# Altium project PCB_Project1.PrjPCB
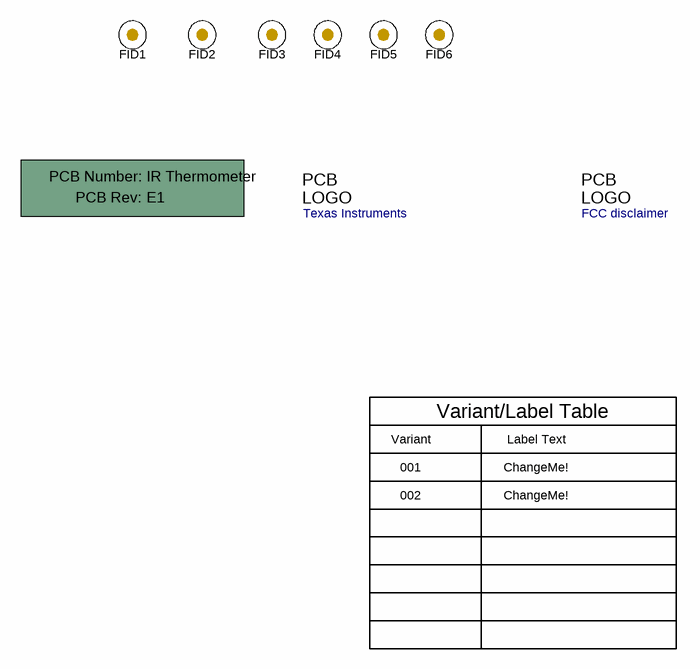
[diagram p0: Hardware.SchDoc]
CopyrightYear: 2018; PCB_Layout: Abhishek Vishwa; PCB_Rev: E1; PRJ_Customer: Public Release; PRJ_Engineer: Abhishek Vishwa; PRJ_Number: IR Thermometer; PRJ_Title: IR Thermometer Design; SCH_Rev: E1; TechSupport: http://www.ti.com/support; TID: N/A
2 sheets, 117 parts. Net scope: flat (ports and power ports of the same name join across sheets).
Board file: PCB.PcbDoc
Sheets:
  Hardware.SchDoc
  Host Controller Section_1.SchDoc

## Sheet Hardware.SchDoc
size 431 x 279 mm; Date: Not shown in title block; ApprovedBy: Not shown in title block; CheckedBy: Not shown in title block; Author: Not shown in title block; CompanyName: Not shown in title block; Engineer: Not shown in title block; Organization: Not shown in title block; Address1: Not shown in title block; Address2: Not shown in title block; Address3: Not shown in title block; Address4: Not shown in title block; DocumentNumber: 5; Revision: Use project parameter SCH_Rev; SheetNumber: 5; SheetTotal: 3; PageSetup: Record=PageOptions¦CenterHorizontal=True¦CenterVertical=True¦PrintScale=1.00¦XCorrection=1.00¦YCorrection=1.00¦PrintKind=0¦BorderSize=5000000¦LeftOffset=0¦BottomOffset=0¦Orientation=2¦PaperLength=1000¦PaperWidth=1000¦Scale=100¦PaperSource=15¦PrintQuality=600¦MediaType=1¦DitherType=10¦PaperKind=Letter¦PrintScaleMode=1

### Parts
!PCB1  Printed Circuit Board  (value not drawn)  (mechanical)
FID1  Fiducial  [Fiducial10-20]  (value not drawn)
FID2  Fiducial  [Fiducial10-20]  (value not drawn)
FID3  Fiducial  [Fiducial10-20]  (value not drawn)
FID4  Fiducial  [Fiducial10-20]  (value not drawn)
FID5  Fiducial  [Fiducial10-20]  (value not drawn)
FID6  Fiducial  [Fiducial10-20]  (value not drawn)
Logo2  Texas Instruments  [TI_Stacked_Overlay_Small]  (no BOM)
Logo3  FCC disclaimer  [FCC_disclaimer]  (no BOM)

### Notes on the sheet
- Variant
- Variant/Label Table
- Label Text
- 001
- 002
- ChangeMe!

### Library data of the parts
!PCB1 = CMP-0003618-2: Manufacturer: Any; PartNumber: IR Thermometer
FID1-FID6 = CMP-0077181-1: Fiducial mark.  There is nothing to buy or mount.
Logo2 = CMP-0074838-1: Texas Instrument Corporate Signature; SymbolCreator: a0412235; Lib Reference: TI_Logo
Logo3 = CMP-0074847-1: FCC_disclaimer

## Sheet Host Controller Section_1.SchDoc
size A2; DocumentNumber: 4; SheetNumber: 4; PageSetup: Record=PageOptions¦CenterHorizontal=True¦CenterVertical=True¦PrintScale=0.69¦XCorrection=1.00¦YCorrection=1.00¦PrintKind=0¦BorderSize=5000000¦LeftOffset=0¦BottomOffset=0¦Orientation=2¦PaperLength=1000¦PaperWidth=1000¦Scale=100¦PaperSource=15¦PrintQuality=600¦MediaType=1¦DitherType=10¦PaperKind=Letter¦PrintScaleMode=1
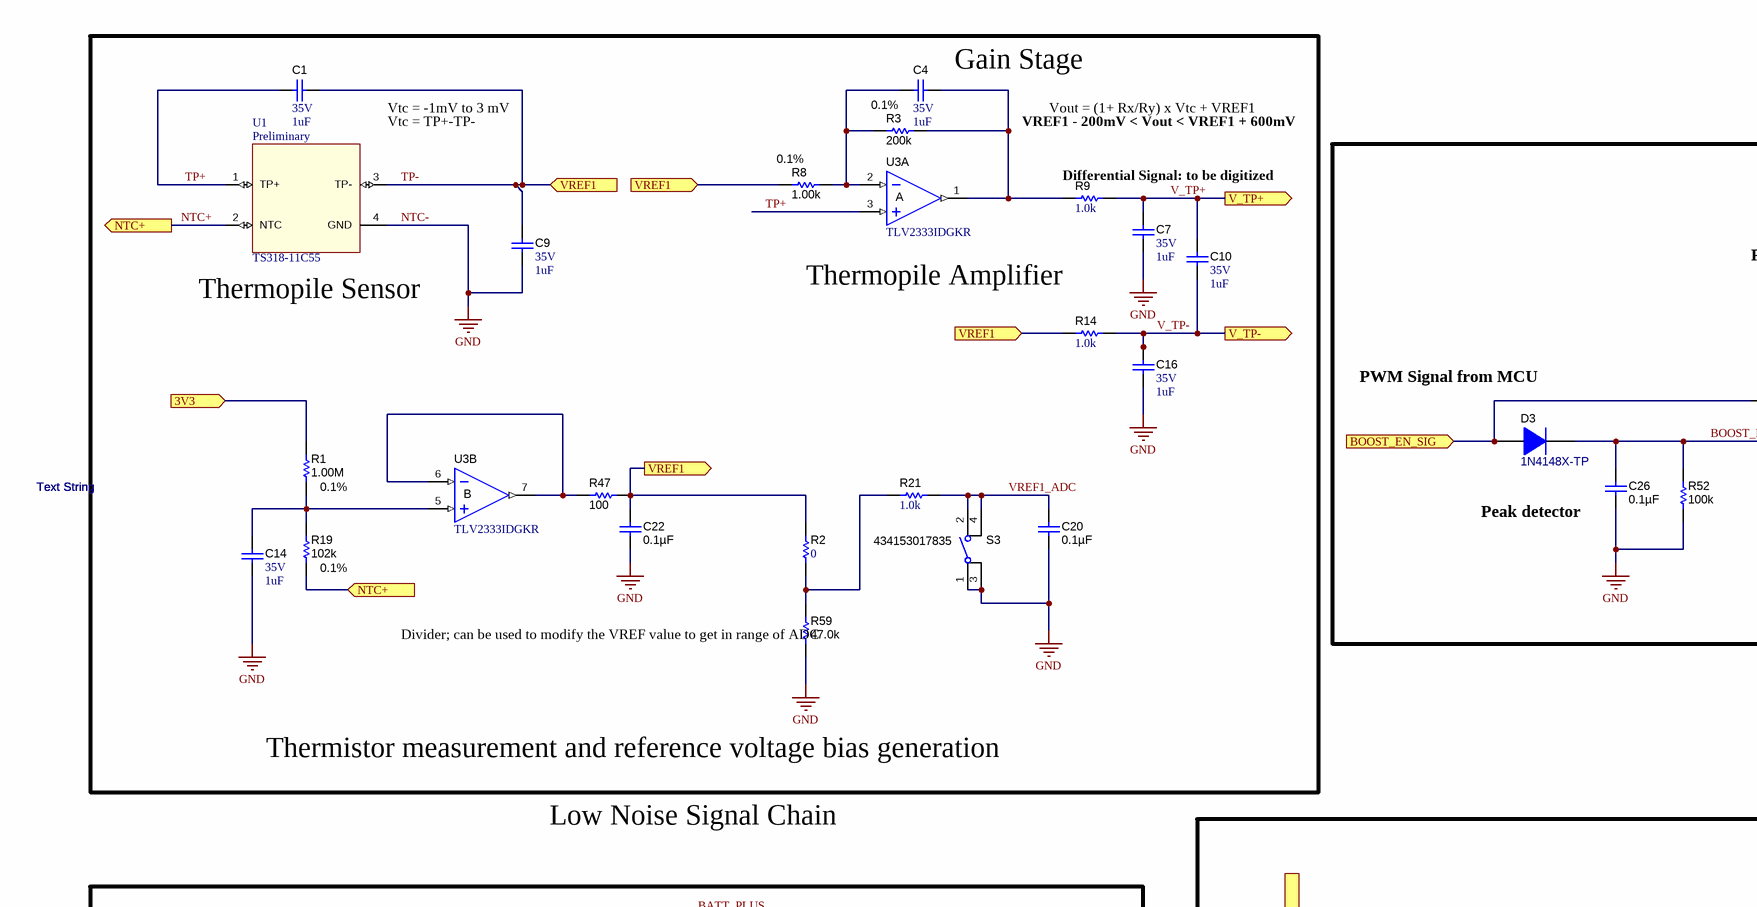
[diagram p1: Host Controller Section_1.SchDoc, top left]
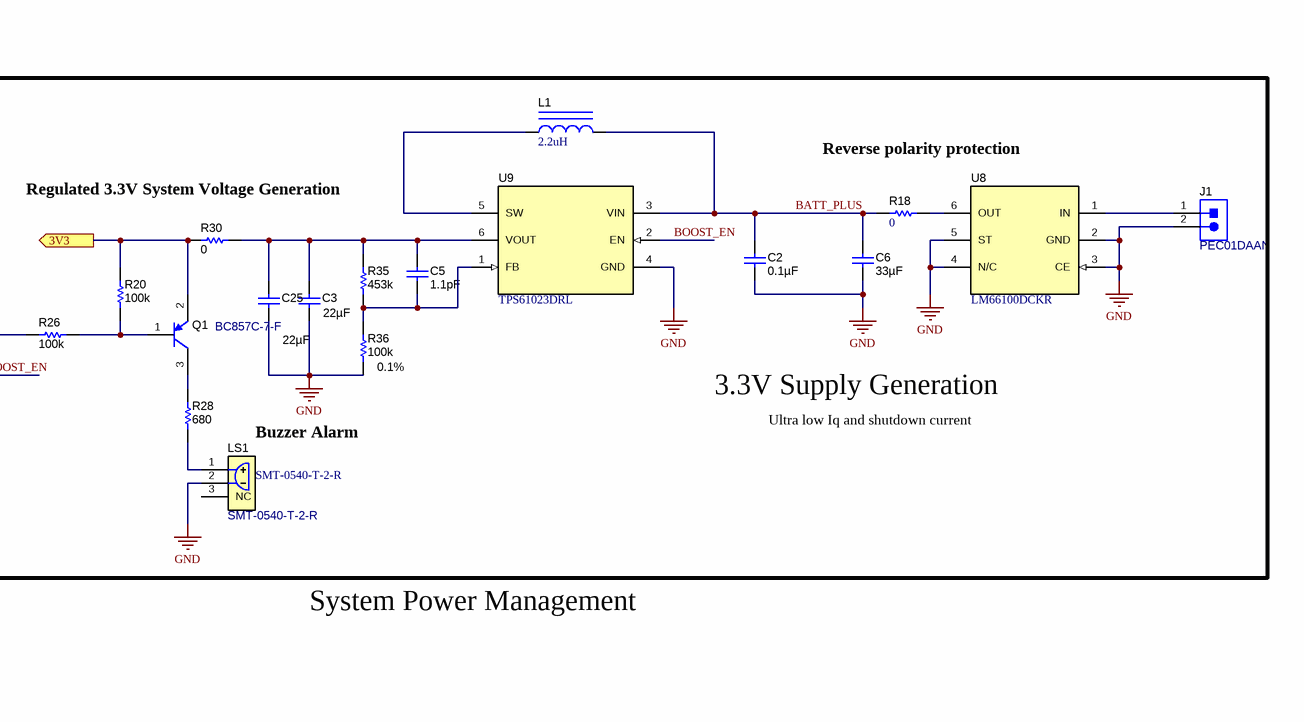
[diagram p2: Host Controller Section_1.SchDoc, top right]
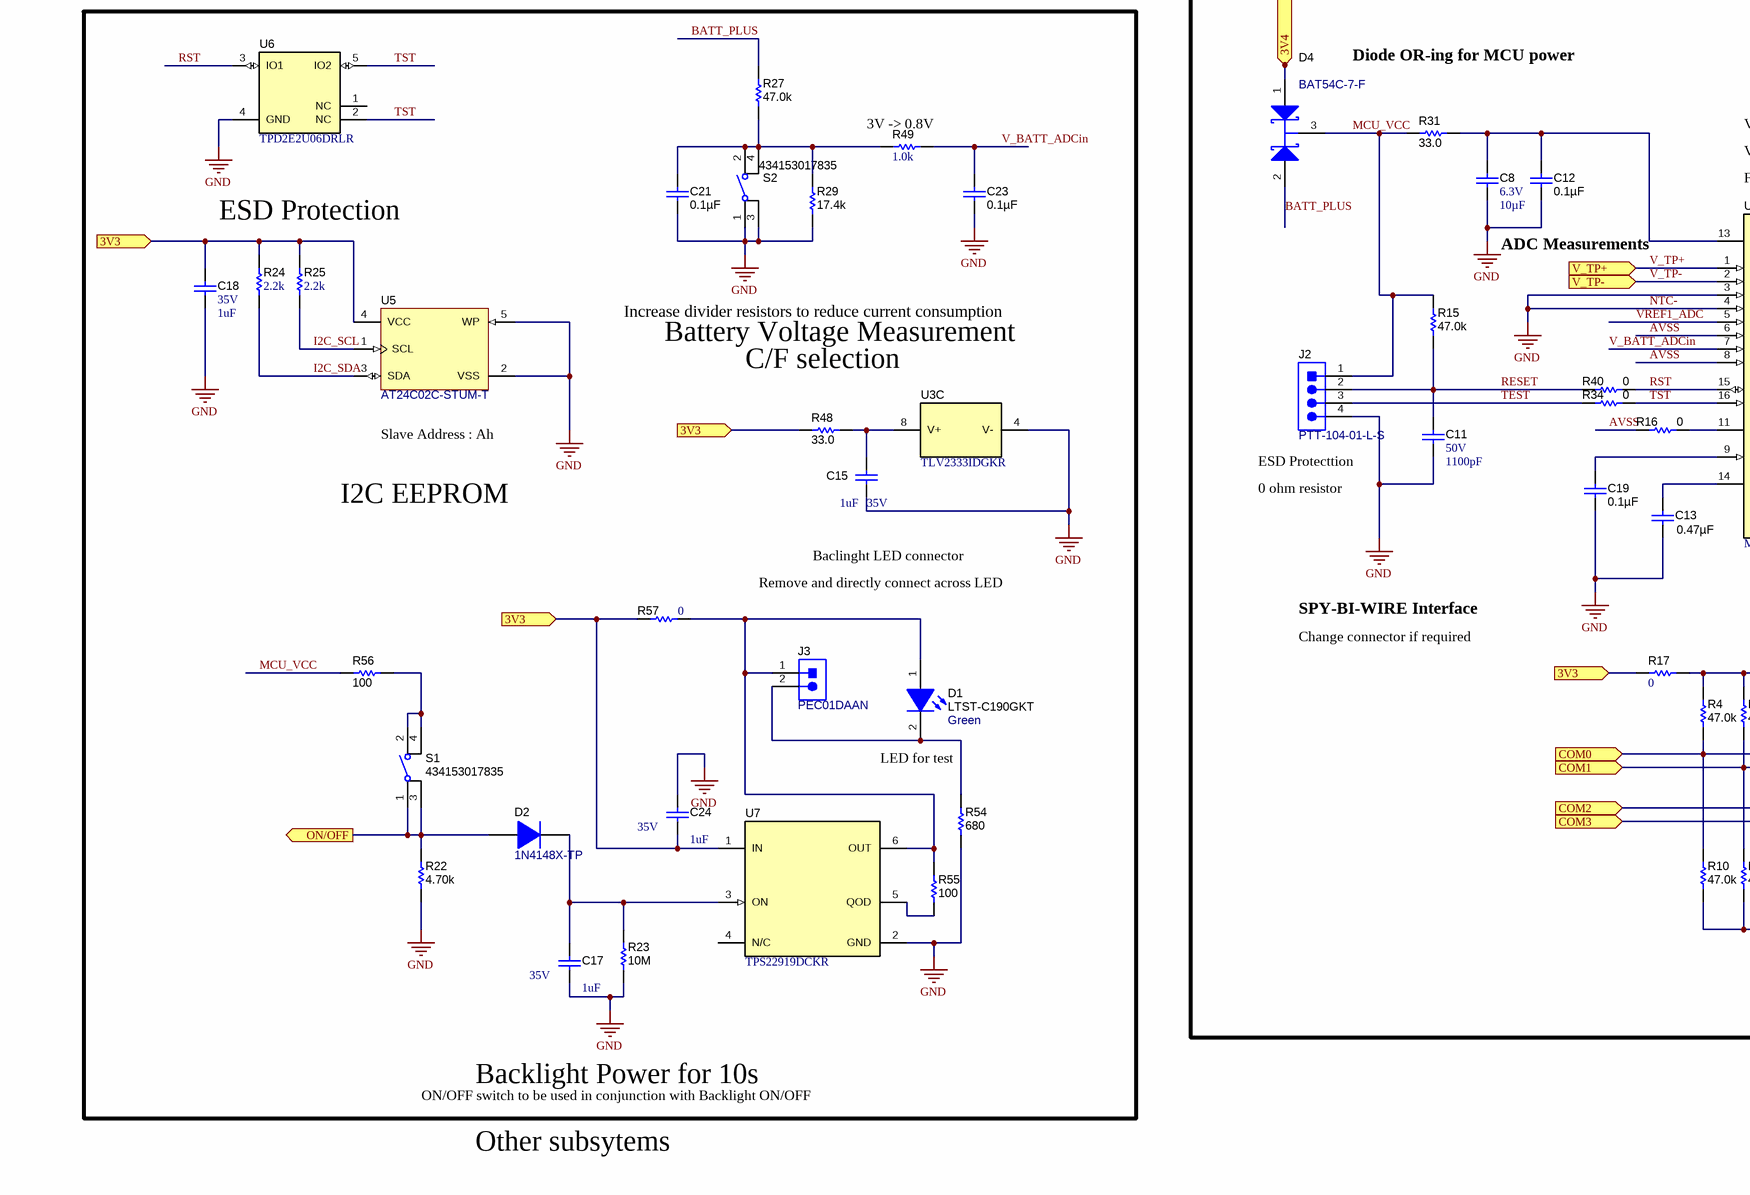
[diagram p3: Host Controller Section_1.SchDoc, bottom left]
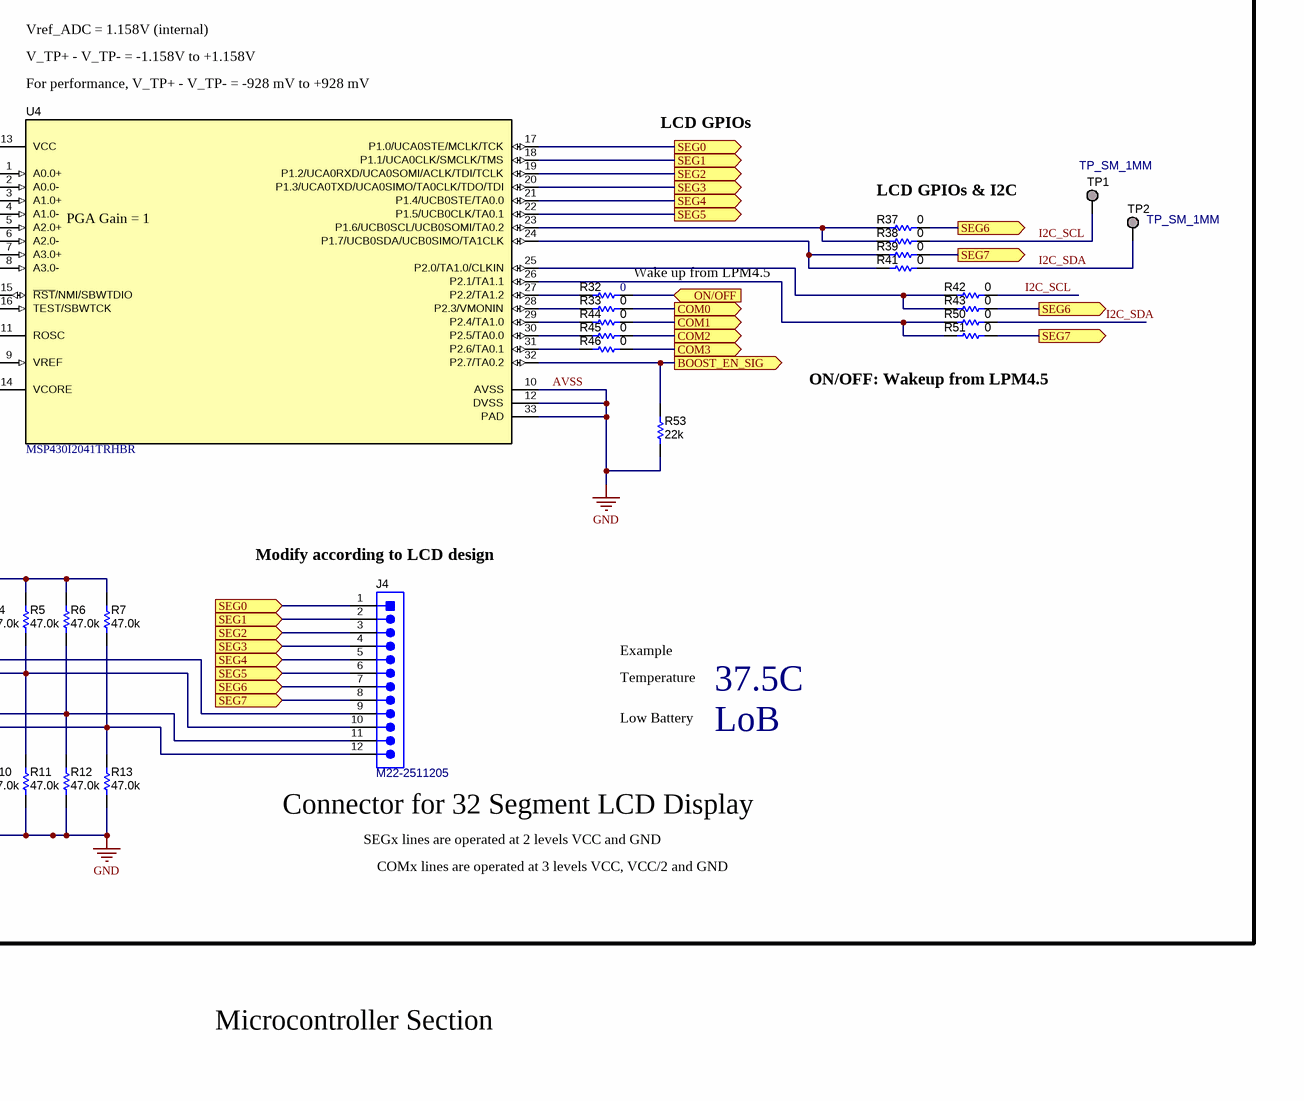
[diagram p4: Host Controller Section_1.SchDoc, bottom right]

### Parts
C1  VDC_V: 35V  ValueDisplayed: 1uF  [0402]  (hidden comment: C1005JB1V105K050BC)
C2  ValueDisplayed: 0.1µF  [0402]  (hidden comment: GRM155R71E104KE14D)
C3  ValueDisplayed: 22µF  [0603]  (hidden comment: GRM188R61A226ME15D)
C4  VDC_V: 35V  ValueDisplayed: 1uF  [0402]  (hidden comment: C1005JB1V105K050BC)
C5  ValueDisplayed: 1.1pF  [0402]  (hidden comment: GRM1555C1H1R1BA01D)
C6  ValueDisplayed: 33µF  [0805_HV]  (hidden comment: C2012X5R1A336M125AC)
C7  VDC_V: 35V  ValueDisplayed: 1uF  [0402]  (hidden comment: C1005JB1V105K050BC)
C8  VDC_V: 6.3V  ValueDisplayed: 10µF  [0402]  (hidden comment: GRM155R60J106ME47D)
C9  VDC_V: 35V  ValueDisplayed: 1uF  [0402]  (hidden comment: C1005JB1V105K050BC)
C10  VDC_V: 35V  ValueDisplayed: 1uF  [0402]  (hidden comment: C1005JB1V105K050BC)
C11  VDC_V: 50V  ValueDisplayed: 1100pF  [0402]  (hidden comment: C0402C112J5GAC7867)
C12  ValueDisplayed: 0.1µF  [0402]  (hidden comment: GRM155R71E104KE14D)
C13  ValueDisplayed: 0.47µF  [0201_033]  (hidden comment: GRM033R60J474KE90D)
C14  VDC_V: 35V  ValueDisplayed: 1uF  [0402]  (hidden comment: C1005JB1V105K050BC)
C15  VDC_V: 35V  ValueDisplayed: 1uF  [0402]  (hidden comment: C1005JB1V105K050BC)
C16  VDC_V: 35V  ValueDisplayed: 1uF  [0402]  (hidden comment: C1005JB1V105K050BC)
C17  VDC_V: 35V  ValueDisplayed: 1uF  [0402]  (hidden comment: C1005JB1V105K050BC)
C18  VDC_V: 35V  ValueDisplayed: 1uF  [0402]  (hidden comment: C1005JB1V105K050BC)
C19  ValueDisplayed: 0.1µF  [0201_033]  (hidden comment: GRM033R61E104KE14J)
C20  ValueDisplayed: 0.1µF  [0402]  (hidden comment: GRM155R71E104KE14D)
C21  ValueDisplayed: 0.1µF  [0402]  (hidden comment: GRM155R71E104KE14D)
C22  ValueDisplayed: 0.1µF  [0402]  (hidden comment: GRM155R71E104KE14D)
C23  ValueDisplayed: 0.1µF  [0402]  (hidden comment: GRM155R71E104KE14D)
C24  VDC_V: 35V  ValueDisplayed: 1uF  [0402]  (hidden comment: C1005JB1V105K050BC)
C25  ValueDisplayed: 22µF  [0603]  (hidden comment: GRM188R61A226ME15D)
C26  ValueDisplayed: 0.1µF  [0402]  (hidden comment: GRM155R71E104KE14D)
D1  LTST-C190GKT  value Green  [LED_LTST-C190]
D2  1N4148X-TP  [SOD-523]
D3  1N4148X-TP  [SOD-523]
D4  BAT54C-7-F  [SOT-23]
J1  PEC01DAAN  [Sullins_PxC01DAAN]
J2  PTT-104-01-L-S  [Samtec_PTT-104-01-x-S]
J3  PEC01DAAN  [Sullins_PxC01DAAN]
J4  M22-2511205  [Harwin_M22-2511205]
L1  ValueDisplayed: 2.2uH  [1008]  (hidden comment: LQM2HPN2R2MG0L)
LS1  SMT-0540-T-2-R  [PUI_SMT-0540-S-R]
Q1  BC857C-7-F  [SOT-23]
R1  Tolerance_%: 0.1%  ValueDisplayed: 1.00M  [CPF_0603]  (hidden comment: CPF0603B1M0E1)
R2  ValueDisplayed: 0  [0402]  (hidden comment: CRCW04020000Z0ED)
R3  ValueDisplayed: 200k  Tolerance_%: 0.1%  [0603]  (hidden comment: RG1608P-204-B-T5)
R4  ValueDisplayed: 47.0k  [0402]  (hidden comment: RC0402FR-0747KL)
R5  ValueDisplayed: 47.0k  [0402]  (hidden comment: RC0402FR-0747KL)
R6  ValueDisplayed: 47.0k  [0402]  (hidden comment: RC0402FR-0747KL)
R7  ValueDisplayed: 47.0k  [0402]  (hidden comment: RC0402FR-0747KL)
R8  ValueDisplayed: 1.00k  Tolerance_%: 0.1%  [0402]  (hidden comment: ERA-2AEB102X)
R9  ValueDisplayed: 1.0k  [0402]  (hidden comment: CRCW04021K00JNED)
R10  ValueDisplayed: 47.0k  [0402]  (hidden comment: RC0402FR-0747KL)
R11  ValueDisplayed: 47.0k  [0402]  (hidden comment: RC0402FR-0747KL)
R12  ValueDisplayed: 47.0k  [0402]  (hidden comment: RC0402FR-0747KL)
R13  ValueDisplayed: 47.0k  [0402]  (hidden comment: RC0402FR-0747KL)
R14  ValueDisplayed: 1.0k  [0402]  (hidden comment: CRCW04021K00JNED)
R15  ValueDisplayed: 47.0k  [0402]  (hidden comment: RC0402FR-0747KL)
R16  ValueDisplayed: 0  [0201]  (hidden comment: ERJ-1GE0R00C)
R17  ValueDisplayed: 0  [0402]  (hidden comment: CRCW04020000Z0ED)
R18  ValueDisplayed: 0  [0402]  (hidden comment: CRCW04020000Z0ED)
R19  ValueDisplayed: 102k  Tolerance_%: 0.1%  [0402]  (hidden comment: RT0402BRD07102KL)
R20  ValueDisplayed: 100k  [0402]  (hidden comment: CRCW0402100KJNED)
R21  ValueDisplayed: 1.0k  [0402]  (hidden comment: CRCW04021K00JNED)
R22  ValueDisplayed: 4.70k  [0402]  (hidden comment: ERJ-2RKF4701X)
R23  ValueDisplayed: 10M  [0402]  (hidden comment: CRCW040210M0JNED)
R24  ValueDisplayed: 2.2k  [0402]  (hidden comment: CRCW04022K20JNED)
R25  ValueDisplayed: 2.2k  [0402]  (hidden comment: CRCW04022K20JNED)
R26  ValueDisplayed: 100k  [0402]  (hidden comment: CRCW0402100KJNED)
R27  ValueDisplayed: 47.0k  [0402]  (hidden comment: RC0402FR-0747KL)
R28  ValueDisplayed: 680  [0402]  (hidden comment: CRCW0402680RJNED)
R29  ValueDisplayed: 17.4k  [0402]  (hidden comment: CRCW040217K4FKED)
R30  ValueDisplayed: 0  [0603]  (hidden comment: ERJ-3GEY0R00V)
R31  ValueDisplayed: 33.0  [0402]  (hidden comment: ERJ-2RKF33R0X)
R32  ValueDisplayed: 0  [0402]  (hidden comment: CRCW04020000Z0ED)
R33  ValueDisplayed: 0  [0201]  (hidden comment: ERJ-1GE0R00C)
R34  ValueDisplayed: 0  [0201]  (hidden comment: ERJ-1GE0R00C)
R35  ValueDisplayed: 453k  [0603]  (hidden comment: RT0603BRD07453KL)
R36  ValueDisplayed: 100k  Tolerance_%: 0.1%  [0402]  (hidden comment: RG1005P-104-B-T5)
R37  ValueDisplayed: 0  [0201]  (hidden comment: ERJ-1GE0R00C)
R38  ValueDisplayed: 0  [0201]  (hidden comment: ERJ-1GE0R00C)
R39  ValueDisplayed: 0  [0201]  (hidden comment: ERJ-1GE0R00C)
R40  ValueDisplayed: 0  [0201]  (hidden comment: ERJ-1GE0R00C)
R41  ValueDisplayed: 0  [0201]  (hidden comment: ERJ-1GE0R00C)
R42  ValueDisplayed: 0  [0201]  (hidden comment: ERJ-1GE0R00C)
R43  ValueDisplayed: 0  [0201]  (hidden comment: ERJ-1GE0R00C)
R44  ValueDisplayed: 0  [0201]  (hidden comment: ERJ-1GE0R00C)
R45  ValueDisplayed: 0  [0201]  (hidden comment: ERJ-1GE0R00C)
R46  ValueDisplayed: 0  [0201]  (hidden comment: ERJ-1GE0R00C)
R47  ValueDisplayed: 100  [0402]  (hidden comment: ERJ-2GEJ101X)
R48  ValueDisplayed: 33.0  [0402]  (hidden comment: ERJ-2RKF33R0X)
R49  ValueDisplayed: 1.0k  [0402]  (hidden comment: CRCW04021K00JNED)
R50  ValueDisplayed: 0  [0201]  (hidden comment: ERJ-1GE0R00C)
R51  ValueDisplayed: 0  [0201]  (hidden comment: ERJ-1GE0R00C)
R52  ValueDisplayed: 100k  [0402]  (hidden comment: CRCW0402100KJNED)
R53  ValueDisplayed: 22k  [0402]  (hidden comment: CRCW040222K0JNED)
R54  ValueDisplayed: 680  [0402]  (hidden comment: CRCW0402680RJNED)
R55  ValueDisplayed: 100  [0402]  (hidden comment: CRCW0402100RJNED)
R56  ValueDisplayed: 100  [0402]  (hidden comment: CRCW0402100RJNED)
R57  ValueDisplayed: 0  [0402]  (hidden comment: CRCW04020000Z0ED)
R59  ValueDisplayed: 47.0k  [0402]  (hidden comment: RC0402FR-0747KL)
S1  434153017835  [SW_434153017835]
S2  434153017835  [SW_434153017835]
S3  434153017835  [SW_434153017835]
TP1  TP_SM_1MM  [TP_SM_1MM]  (no BOM)
TP2  TP_SM_1MM  [TP_SM_1MM]  (no BOM)
U1  TS318-11C55  [TE_TS318-11C55]
U3  TLV2333IDGKR  [DGK0008A_N]  (parts A,B,C of 3)
U4  MSP430I2041TRHBR  [RHB0032M]
U5  AT24C02C-STUM-T  [SOT-23-5]
U6  TPD2E2U06DRLR  [DRL0005A]
U7  TPS22919DCKR  [DCK0006A_N]
U8  LM66100DCKR  [DCK0006A_N]
U9  TPS61023DRL  [DRL0006A]

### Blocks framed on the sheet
3.3V Supply Generation: C2 C3 C5 C6 C25 C26 D3 J1 L1 LS1 Q1 R18 R20 R26 R28 R30 R35 R36 R52 U8 U9

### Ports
3V3 (in), 3V3 (out), 3V4 (in), BOOST_EN_SIG (in), BOOST_EN_SIG (out), COM0 (in), COM0 (out), COM1 (in), COM1 (out), COM2 (in), COM2 (out), COM3 (in), COM3 (out), NTC+ (in), NTC+ (out), ON/OFF (in), ON/OFF (out), SEG0 (in), SEG0 (out), SEG1 (in), SEG1 (out), SEG2 (in), SEG2 (out), SEG3 (in), SEG3 (out), SEG4 (in), SEG4 (out), SEG5 (in), SEG5 (out), SEG6 (in), SEG6 (out), SEG7 (in), SEG7 (out), V_TP+ (in), V_TP+ (out), V_TP- (in), V_TP- (out), VREF1 (in), VREF1 (out)

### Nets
AVSS: C2.2 C3.2 C6.2 C7.2 C8.2 C9.2 C11.2 C12.2 C13.2 C14.2 C15.2 C16.2 C17.2 C18.2 C19.2 C20.2 C21.2 C22.2 C23.2 C24.1 C25.2 C26.2 J1.2 J2.4 LS1.2(-) R10.1 R11.1 R12.1 R13.1 R16.1 R22.1 R23.1 R29.1 R36.1 R52.1 R53.1 R54.1 R59.1 S2.1 S2.3 S3.1 S3.3 U1.4(GND) U3.4(V-) U4.3(A1.0+) U4.4(A1.0-) U4.6(A2.0-) U4.8(A3.0-) U4.10(AVSS) U4.12(DVSS) U4.33(PAD) U5.2(VSS) U5.5(WP) U6.4(GND) U7.2(GND) U8.2(GND) U8.3(CE) U8.4(N/C) U8.5(ST) U9.4(GND)  [also labelled GND, NTC-]
3V3: C18.1 C24.2 D4.1(A1) Q1.2(E) R1.2 R17.2 R20.2 R24.2 R25.2 R30.1 R48.1 R57.2 U5.4(VCC) U7.1(IN) ; port 3V3, port 3V4
BATT_PLUS: C2.1 C6.1 D4.2(A2) L1.2 R18.2 R27.2 U9.3(VIN)
BOOST_EN: C26.1 D3.1(K) R52.2 U9.2(EN)
BOOST_EN_SIG: D3.2(A) R26.1 R53.2 U4.32(P2.7/TA0.2) ; port BOOST_EN_SIG
COM0: J4.9 R4.1 R10.2 R33.2 ; port COM0
COM1: J4.10 R5.1 R11.2 R44.2 ; port COM1
COM2: J4.11 R6.1 R12.2 R45.2 ; port COM2
COM3: J4.12 R7.1 R13.2 R46.2 ; port COM3
I2C_SCL: R25.1 R38.2 R42.2 TP1.1 U5.1(SCL)
I2C_SDA: R24.1 R41.2 R50.2 TP2.1 U5.3(SDA)
MCU_VCC: D4.3(K) J2.1 R15.2 R31.1 R56.2
NTC+: R19.1 U1.2(NTC) ; port NTC+
ON/OFF: D2.2(A) R22.2 R32.1 S1.1 S1.3 ; port ON/OFF
RESET: C11.1 J2.2 R15.1 R40.1
RST: R40.2 U4.15(~{RST}/NMI/SBWTDIO) U6.3(IO1)
SEG0: J4.1 U4.17(P1.0/UCA0STE/MCLK/TCK) ; port SEG0
SEG1: J4.2 U4.18(P1.1/UCA0CLK/SMCLK/TMS) ; port SEG1
SEG2: J4.3 U4.19(P1.2/UCA0RXD/UCA0SOMI/ACLK/TDI/TCLK) ; port SEG2
SEG3: J4.4 U4.20(P1.3/UCA0TXD/UCA0SIMO/TA0CLK/TDO/TDI) ; port SEG3
SEG4: J4.5 U4.21(P1.4/UCB0STE/TA0.0) ; port SEG4
SEG5: J4.6 U4.22(P1.5/UCB0CLK/TA0.1) ; port SEG5
SEG6: J4.7 R37.2 R43.2 ; port SEG6
SEG7: J4.8 R39.2 R51.2 ; port SEG7
TEST: J2.3 R34.1
TP+: C1.1 U1.1(TP+) U3.3(IN+)
TP-: C1.2 C9.1 C22.1 R2.1 R8.1 R14.1 R47.2 U1.3(TP-) ; port VREF1
TST: R34.2 U4.16(TEST/SBWTCK) U6.2(NC) U6.5(IO2)
V_BATT_ADCin: C23.1 R49.2 U4.7(A3.0+)
V_TP+: C7.1 C10.1 R9.2 U4.1(A0.0+) ; port V_TP+
V_TP-: C10.2 C16.1 R14.2 U4.2(A0.0-) ; port V_TP-
VREF1_ADC: C20.1 R21.2 S3.2 S3.4 U4.5(A2.0+)
NetC3_1: C3.1 C5.2 C25.1 R30.2 R35.2 U9.6(VOUT)
NetC4_1: C4.1 R3.1 R8.2 U3.2(IN-)
NetC4_2: C4.2 R3.2 R9.1 U3.1(OUT)
NetC5_1: C5.1 R35.1 R36.2 U9.1(FB)
NetC8_1: C8.1 C12.1 R31.2 U4.13(VCC)
NetC13_1: C13.1 U4.14(VCORE)
NetC14_1: C14.1 R1.1 R19.2 U3.5(IN+)
NetC15_1: C15.1 R48.2 U3.8(V+)
NetC17_1: C17.1 D2.1(K) R23.2 U7.3(ON)
NetC19_1: C19.1 U4.9(VREF)
NetC21_1: C21.1 R27.1 R29.2 R49.1 S2.2 S2.4
NetD1_1: D1.1(A) J3.1 R55.2 R57.1 U7.6(OUT)
NetD1_2: D1.2(K) J3.2 R54.2
NetJ1_1: J1.1 U8.1(IN)
NetL1_1: L1.1 U9.5(SW)
NetLS1_1: LS1.1(+) R28.1
NetQ1_1: Q1.1(B) R20.1 R26.2
NetQ1_3: Q1.3(C) R28.2
NetR2_2: R2.2 R21.1 R59.2
NetR4_2: R4.2 R5.2 R6.2 R7.2 R17.1
NetR16_2: R16.2 U4.11(ROSC)
NetR18_1: R18.1 U8.6(OUT)
NetR32_2: R32.2 U4.27(P2.2/TA1.2)
NetR33_1: R33.1 U4.28(P2.3/VMONIN)
NetR37_1: R37.1 R38.1 U4.23(P1.6/UCB0SCL/UCB0SOMI/TA0.2)
NetR39_1: R39.1 R41.1 U4.24(P1.7/UCB0SDA/UCB0SIMO/TA1CLK)
NetR42_1: R42.1 R43.1 U4.25(P2.0/TA1.0/CLKIN)
NetR44_1: R44.1 U4.29(P2.4/TA1.0)
NetR45_1: R45.1 U4.30(P2.5/TA0.0)
NetR46_1: R46.1 U4.31(P2.6/TA0.1)
NetR47_1: R47.1 U3.6(IN-) U3.7(OUT)
NetR50_1: R50.1 R51.1 U4.26(P2.1/TA1.1)
NetR55_1: R55.1 U7.5(QOD)
NetR56_1: R56.1 S1.2 S1.4

Not connected (* = marked no-connect by the designer): LS1 3(NC); U6 1(NC); U7 4(N/C)

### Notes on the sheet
- (near C4) Gain Stage
- Vtc = TP+-TP-
- Vtc = -1mV to 3 mV
- VREF1 - 200mV < Vout < VREF1 + 600mV
- Vout = (1+ Rx/Ry) x Vtc + VREF1
- (near R9) Differential Signal: to be digitized
- Reverse polarity protection
- (near U1) Thermopile Sensor
- Thermopile Amplifier
- (near R30) Regulated 3.3V System Voltage Generation
- PWM Signal from MCU
- Text String
- (near LS1) Buzzer Alarm
- Ultra low Iq and shutdown current
- (near C26) Peak detector
- (near R59) Divider; can be used to modify the VREF value to get in range of ADC
- System Power Management
- Thermistor measurement and reference voltage bias generation
- Low Noise Signal Chain
- Diode OR-ing for MCU power
- (near R49) 3V -> 0.8V
- Vref_ADC = 1.158V (internal)
- V_TP+ - V_TP- = -1.158V to +1.158V
- ESD Protection
- For performance, V_TP+ - V_TP- = -928 mV to +928 mV
- LCD GPIOs
- ADC Measurements
- LCD GPIOs & I2C
- Increase divider resistors to reduce current consumption
- Battery Voltage Measurement
- C/F selection
- (near U4) PGA Gain = 1
- Wake up from LPM4.5
- (near U5) Slave Address : Ah
- I2C EEPROM
- (near J2) ESD Protecttion
- 0 ohm resistor
- ON/OFF: Wakeup from LPM4.5
- Baclinght LED connector
- Remove and directly connect across LED
- SPY-BI-WIRE Interface
- Change connector if required
- (near J4) Modify according to LCD design
- LED for test
- Example
- Temperature
- Low Battery
- 37.5C
- LoB
- (near J4) Connector for 32 Segment LCD Display
- SEGx lines are operated at 2 levels VCC and GND
- COMx lines are operated at 3 levels VCC, VCC/2 and GND
- ON/OFF switch to be used in conjunction with Backlight ON/OFF
- Backlight Power for 10s
- Other subsytems
- Microcontroller Section

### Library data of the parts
C1 C4 C7 C9 C10 C14-C18 C24 = CMP-0006253-2: CAP, CERM, 1 uF, 35 V, +/- 10%, JB, 0402; Manufacturer: TDK; TaMin_C: -25°C; Polarized: N; SizeAreaWB_mm2: 3; Value1: Unknown; U/M: EA; Value: 1uF; TaMax_C: 85°C; SizeZ_mm: 0.6; SizeX_mm: 1; SizeY_mm: 0.5; Cap_F: 1µF; AEC Category: Q200
C2 C12 C20-C23 C26 = GRM155R71E104KE14D: CAP, CERM, 0.1 µF, 25 V,+/- 10%, X7R, 0402; Manufacturer: MuRata; Polarized: N; CompType: Capacitor; Value: 0.1uF; U/M: EA; Cap_F: 0.0000001; Tolerance_%: 10; VDC_V: 25; Value2: 25V; TaMin_C: -55; TaMax_C: 125; SizeArea_mm2: 0.5; SizeAreaWB_mm2: 3; SizeX_mm: 1; SizeZ_mm: 0.6; AEC Category: Q200; Green_Lifecycle: Active; Green_REACh: Passed
C3 C25 = GRM188R61A226ME15D: CAP, CERM, 22 µF, 10 V,+/- 20%, X5R, 0603; Manufacturer: MuRata; Polarized: N; CompType: Capacitor; Value: 22uF; U/M: EA; Cap_F: 0.000022; Tolerance_%: 20; VDC_V: 10; Value2: 10V; TaMin_C: -55; TaMax_C: 85; SizeArea_mm2: 1.28; SizeAreaWB_mm2: 4.68; SizeX_mm: 1.6; SizeY_mm: 0.8; SizeZ_mm: 1; AEC Category: Q200; Green_Lifecycle: Active; Green_REACh: Passed
C5 = GRM1555C1H1R1BA01D: CAP, CERM, 1.1 pF, 50 V,+/- 10%, C0G/NP0, 0402; Manufacturer: MuRata; Polarized: N; CompType: Capacitor; Value: 1.1pF; U/M: EA; Cap_F: 0.0000000000011; Tolerance_%: 10; VDC_V: 50; Value2: 50V; TaMin_C: -55; TaMax_C: 125; SizeArea_mm2: 0.5; SizeAreaWB_mm2: 3; SizeX_mm: 1; SizeZ_mm: 0.6; AEC Category: Q200
C6 = C2012X5R1A336M125AC: CAP, CERM, 33 µF, 10 V,+/- 20%, X5R, 0805; Manufacturer: TDK; Polarized: N; CompType: Capacitor; Value: 33uF; U/M: EA; Cap_F: 0.000033; Tolerance_%: 20; ESR_ohm: 0.001694; Value1: 0.001694 ohm; VDC_V: 10; Value2: 10V; IRMS_A: 5.01281; TaMin_C: -55; TaMax_C: 85; Cap_Case: 0805; SizeArea_mm2: 2.5; SizeAreaWB_mm2: 6.75; SizeX_mm: 2; SizeY_mm: 1.25; SizeZ_mm: 1.45; AEC Category: Q200; Green_Lifecycle: Active; Green_REACh: Passed
C8 = CMP-0078624-1: CAP, CERM, 10 µF, 6.3 V,+/- 20%, X5R, 0402; Manufacturer: MuRata; SizeAreaWB_mm2: 3; SizeArea_mm2: 0.5; AEC Qualified: N; AEC Category: Q200; Value: 10uF; TaMax_C: 85°C; SizeZ_mm: 0.6; TaMin_C: -55°C; U/M: EA; SizeX_mm: 1
C11 = CMP-0006238-2: CAP, CERM, 1100 pF, 50 V, +/- 5%, C0G/NP0, 0402; Manufacturer: Kemet; TaMin_C: -55°C; Polarized: N; SizeAreaWB_mm2: 3; Value1: Unknown; U/M: EA; Value: 1100pF; TaMax_C: 125°C; SizeZ_mm: 0.6; SizeX_mm: 1; SizeY_mm: 0.5; Cap_F: 1.1nF; AEC Category: Q200
C13 = GRM033R60J474KE90D: CAP, CERM, 0.47 µF, 6.3 V,+/- 10%, X5R, 0201; Manufacturer: MuRata; Polarized: N; CompType: Capacitor; Value: 0.47uF; U/M: EA; Cap_F: 0.00000047; Tolerance_%: 10; VDC_V: 6.3; Value2: 6.3V; TaMin_C: -55; TaMax_C: 85; Cap_Case: 0201; SizeArea_mm2: 0.18; SizeAreaWB_mm2: 2.08; SizeX_mm: 0.6; SizeY_mm: 0.3; SizeZ_mm: 0.33; AEC Category: Q200
C19 = GRM033R61E104KE14J: CAP, CERM, 0.1 µF, 25 V,+/- 10%, X5R, 0201; Manufacturer: MuRata; Polarized: N; CompType: Capacitor; Value: 0.1uF; U/M: EA; Cap_F: 0.0000001; Tolerance_%: 10; VDC_V: 25; Value2: 25V; TaMin_C: -55; TaMax_C: 85; Cap_Case: 0201; SizeArea_mm2: 0.18; SizeAreaWB_mm2: 2.08; SizeX_mm: 0.6; SizeY_mm: 0.3; SizeZ_mm: 0.33; AEC Category: Q200; Green_Lifecycle: Active; Green_REACh: Passed
D1 = CMP-0002827-2: LED, Green, SMD; Manufacturer: Lite-On; Io_A: 20mA; Power_TotalModule: 100mW; Value1: 0.1W; U/M: EA; Vf_V: 2.1V
D2 D3 = CMP-0076957-1: Diode, Switching, 75 V, 0.3 A, SOD-523; Manufacturer: Micro Commercial Components; SizeAreaWB_mm2: 5.13; Vr_V: 75V; SizeArea_mm2: 1.53; TJmax_C: 150°C; AEC Category: Q101; Value: 75V; SizeZ_mm: 0.65; Green_REACh: Incomplete; Io_A: 300mA; Vf_V: 1.25V; SizeY_mm: 0.9; Green_Lifecycle: Not Set; U/M: EA; Value1: 0.3A; SizeX_mm: 1.7
D4 = CMP-0028453-2: Diode, Schottky, 30 V, 0.2 A, SOT-23; Manufacturer: Diodes Inc.; Vr_V: 30V; Green_Lifecycle: Active; Vf_V: 650mV; Value: 30V; SizeZ_mm: 1.1; SizeAreaWB_mm2: 14; TJmax_C: 125°C; Io_A: 200mA; Value2: 0.65V; SizeY_mm: 3; AEC Category: Q101; SizeX_mm: 2.5; Green_REACh: Passed; Value1: 0.2A; SizeArea_mm2: 7.5
J1 J3 = CMP-0054594-1: Header, 2.54mm, 1x2, Tin, Black, TH; Manufacturer: Sullins Connector Solutions; CNHeader: TRUE; Current_A: 3A; Green_Lifecycle: Active; Shrouded: N; Gender: Male; Green_REACh: Passed; Voltage_V: 1.8kV; Row_Count: 2; RowSpacing_mm: 2.54; CT: FALSE; Cert_UL: Y
J2 = CMP-0055572-1: Header, 2mm, 4x1, Gold, TH; Manufacturer: Samtec; CNHeader: TRUE; Current_A: 2.9A; Shrouded: N; Gender: Male; Row_Count: 1; Pitch_mm: 2; CT: FALSE; Cert_UL: Y
J4 = CMP-0075238-1: Header, 2mm, 12x1, Gold, TH; Manufacturer: Harwin; CNHeader: True; Current_A: 1A; Shrouded: N; Gender: Male; Voltage_V: 500V; Row_Count: 1; Pitch_mm: 2; CT: False; Cert_UL: Y
L1 = CMP-0058752-1: Inductor, Multilayer, Ferrite, 2.2 uH, 1.3 A, 0.08 ohm, SMD; Manufacturer: MuRata; Irms: 1.3A @ 40C rise; Green_Lifecycle: Active; SizeAreaWB_mm2: 10.5; DCR_ohm: 0.08; Green_REACh: Passed; Value: 2.2uH; Imax_A: 1.3A; SizeZ_mm: 1.2; SizeX_mm: 2.5; SizeY_mm: 2; SizeArea_mm2: 5; Ind_H: 2.2µH; AEC Category: Q200
LS1 = CMP-0001959-1: Buzzer, 2 to 4V, 4kHz, SMD; Manufacturer: PUI Audio; SizeZ_mm: 2.1; SizeX_mm: 5; SizeY_mm: 5.5; SizeAreaWB_mm2: 52.5; SizeArea_mm2: 27.5
Q1 = CMP-0000316-2: Transistor, PNP, 45 V, 0.1 A, SOT-23; Manufacturer: Diodes Inc.; TaMax_C: 150°C; Value2: 600; Value1: 0.1 A; Vcesat1_V: 75mV; SizeX_mm: 2.5; SizeY_mm: 3; TaMin_C: -65°C; IcRated_A: 100mA; CompType: BJT; SizeZ_mm: 1.1; Value: 45 V; SizeArea_mm2: 7.5; NPN: 0; Vceo_V: 45V; PNP: 1; AEC Category: Q101; SizeAreaWB_mm2: 14; U/M: EA
R1 = CMP-0079989-2: RES, 1.00 M, 0.1%, 0.063 W, 0603; Manufacturer: TE Connectivity; Value_Code: 1M00; SizeAreaWB_mm2: 4.68; SizeArea_mm2: 1.28; AEC Qualified: N; AEC Category: Q200; Res_ohm: 1M; Value: 1.00Meg; SizeZ_mm: 1; Green_REACh: Incomplete; EIA_Code: E192; TempCo: 25 ppm/C; Power_W: 63mW; VDC_V: 50V; SizeY_mm: 0.8; Value2: 0.063W; Green_Lifecycle: Active; SizeX_mm: 1.6
R2 R17 R18 R32 R57 = CMP-0026822-1: RES, 0, 5%, 0.063 W, 0402; Manufacturer: Vishay-Dale; Power_W: 63mW; TempCo: 200 ppm/C; Value_Code: 0000; U/M: EA; Value: 0; EIA_Code: E24; SizeX_mm: 1; SizeY_mm: 0.5; SizeZ_mm: 0.6; Value2: 0.063W; VDC_V: 50V; AEC Category: Q200
R3 = RG1608P-204-B-T5: RES, 200 k, 0.1%, 0.1 W, 0603; Manufacturer: Susumu Co Ltd; CompType: Resistor; Value: 200k; Res_ohm: 200000; Power_W: 0.1; Value2: 0.1W; VDC_V: 75; TempCo: 25 ppm/C; SizeArea_mm2: 1.28; SizeX_mm: 1.6; SizeY_mm: 0.8; SizeZ_mm: 1; EIA_Code: E192; U/M: EA; AEC Category: Q200
R4-R7 R10-R13 R15 R27 R59 = RC0402FR-0747KL: RES, 47.0 k, 1%, 0.0625 W, 0402; Manufacturer: Yageo America; CompType: Resistor; Value: 47.0k; Res_ohm: 47000; Value_Code: 47k0; Tolerance_%: 1; Power_W: 0.0625; VDC_V: 50; TempCo: 100 ppm/C; SizeArea_mm2: 0.5; SizeZ_mm: 0.6; U/M: EA; AEC Category: Q200; AEC Qualified: N; Green_Lifecycle: Active; Green_REACh: Passed
R8 = ERA-2AEB102X: RES, 1.00 k, 0.1%, 0.063 W, 0402; Manufacturer: Panasonic; CompType: Resistor; Value: 1.00k; Res_ohm: 1000; Value_Code: 1k00; Power_W: 0.063; Value2: 0.063W; VDC_V: 50; TempCo: 25 ppm/C; SizeArea_mm2: 0.5; SizeX_mm: 1; SizeZ_mm: 0.6; EIA_Code: E192; U/M: EA; AEC Category: Q200; Green_Lifecycle: Active; Green_REACh: Passed
R9 R14 R21 R49 = CMP-0026852-3: RES, 1.0 k, 5%, 0.063 W, AEC-Q200 Grade 0, 0402; Manufacturer: Vishay-Dale; Power_W: 63mW; TempCo: 200 ppm/C; Value_Code: 1k00; Value: 1.0k; EIA_Code: E24; Res_ohm: 1k; SizeX_mm: 1; SizeY_mm: 0.5; SizeZ_mm: 0.6; Value2: 0.063W; AEC Qualified: Y; VDC_V: 50V; AEC Category: Q200; AEC Grade: 0
R16 R33 R34 R37-R46 R50 R51 = ERJ-1GE0R00C: RES, 0, 5%, 0.05 W, 0201; Manufacturer: Panasonic; CompType: Resistor; Value: 0; Value_Code: 0000; Tolerance_%: 5; Power_W: 0.05; Value2: 0.05W; VDC_V: 15; TempCo: 600 ppm/C; SizeArea_mm2: 0.18; SizeX_mm: 0.6; SizeY_mm: 0.3; SizeZ_mm: 0.26; EIA_Code: E24; U/M: EA; AEC Category: Q200
R19 = RG1005P-104-B-T5: RES, 100 k, 0.1%, 0.063 W, 0402; Manufacturer: Yageo; CompType: Resistor; Value: 102k; Res_ohm: 100000; Power_W: 0.063; Value2: 0.063W; TempCo: 25 ppm/C; SizeArea_mm2: 0.5; SizeX_mm: 1; SizeZ_mm: 0.6; EIA_Code: E192; U/M: EA; AEC Category: Q200; Green_Lifecycle: Active; Green_REACh: Passed
R20 R26 R52 = CRCW0402100KJNED: RES, 100 k, 5%, 0.063 W, 0402; Manufacturer: Vishay-Dale; CompType: Resistor; Value: 100k; Res_ohm: 100000; Tolerance_%: 5; Power_W: 0.063; Value2: 0.063W; VDC_V: 50; TempCo: 200 ppm/C; SizeArea_mm2: 0.5; SizeX_mm: 1; SizeZ_mm: 0.6; EIA_Code: E24; U/M: EA; AEC Category: Q200; Green_Lifecycle: Active; Green_REACh: Passed
R22 = ERJ-2RKF4701X: RES, 4.70 k, 1%, 0.1 W, 0402; Manufacturer: Panasonic; CompType: Resistor; Value: 4.70k; Res_ohm: 4700; Value_Code: 4k70; Tolerance_%: 1; Power_W: 0.1; Value2: 0.1W; VDC_V: 50; TempCo: 100 ppm/C; SizeArea_mm2: 0.5; SizeZ_mm: 0.6; U/M: EA; AEC Category: Q200; Green_Lifecycle: Active; Green_REACh: Passed
R23 = CRCW040210M0JNED: RES, 10 M, 5%, 0.063 W, 0402; Manufacturer: Vishay-Dale; CompType: Resistor; Value: 10Meg; Res_ohm: 10000000; Value_Code: 10M0; Tolerance_%: 5; Power_W: 0.063; Value2: 0.063W; VDC_V: 50; TempCo: 200 ppm/C; SizeArea_mm2: 0.5; SizeX_mm: 1; SizeZ_mm: 0.6; EIA_Code: E24; U/M: EA; AEC Category: Q200; Green_Lifecycle: Active; Green_REACh: Passed
R24 R25 = CMP-0026890-3: RES, 2.2 k, 5%, 0.063 W, 0402; Manufacturer: Vishay-Dale; Power_W: 63mW; TempCo: 200 ppm/C; Value_Code: 2k20; U/M: EA; Value: 2.2k; EIA_Code: E24; SizeX_mm: 1; SizeY_mm: 0.5; SizeZ_mm: 0.6; Value2: 0.063W; VDC_V: 50V; AEC Category: Q200
R28 R54 = CRCW0402680RJNED: RES, 680, 5%, 0.063 W, 0402; Manufacturer: Vishay-Dale; CompType: Resistor; Value: 680; Value_Code: 680R; Tolerance_%: 5; Power_W: 0.063; Value2: 0.063W; VDC_V: 50; TempCo: 200 ppm/C; SizeArea_mm2: 0.5; SizeX_mm: 1; SizeZ_mm: 0.6; EIA_Code: E24; U/M: EA; AEC Category: Q200
R29 = CRCW040217K4FKED: RES, 17.4 k, 1%, 0.063 W, 0402; Manufacturer: Vishay-Dale; CompType: Resistor; Value: 17.4k; Res_ohm: 17400; Value_Code: 17k4; Tolerance_%: 1; Power_W: 0.063; Value2: 0.063W; VDC_V: 50; TempCo: 100 ppm/C; SizeArea_mm2: 0.5; SizeZ_mm: 0.6; EIA_Code: E96; U/M: EA; AEC Category: Q200; Green_Lifecycle: Active; Green_REACh: Passed
R30 = ERJ-3GEY0R00V: RES, 0, 5%, 0.1 W, 0603; Manufacturer: Panasonic; CompType: Resistor; Value: 0; Value_Code: 0000; Tolerance_%: 5; Power_W: 0.1; Value2: 0.1W; VDC_V: 50; TempCo: 600 ppm/C; SizeArea_mm2: 1.28; SizeX_mm: 1.6; SizeY_mm: 0.8; SizeZ_mm: 1; EIA_Code: E24; U/M: EA; AEC Category: Q200; Green_Lifecycle: Active; Green_REACh: Passed
R31 R48 = ERJ-2RKF33R0X: RES, 33.0, 1%, 0.1 W, 0402; Manufacturer: Panasonic; CompType: Resistor; Value: 33.0; Res_ohm: 33; Value_Code: 33R0; Tolerance_%: 1; Power_W: 0.1; Value2: 0.1W; VDC_V: 50; TempCo: 100 ppm/C; SizeArea_mm2: 0.5; SizeZ_mm: 0.6; U/M: EA; AEC Category: Q200; Green_Lifecycle: Active; Green_REACh: Passed
R35 = RT0603BRD07453KL: RES, 453 k, 0.1%, 0.1 W, 0603; Manufacturer: Yageo America; CompType: Resistor; Value: 453k; Res_ohm: 453000; Tolerance_%: 0.1; Value2: 0.1W; VDC_V: 75; TempCo: 25 ppm/C; SizeArea_mm2: 1.28; SizeX_mm: 1.6; SizeY_mm: 0.8; SizeZ_mm: 1; EIA_Code: E192; U/M: EA; AEC Category: Q200
R36 = RG1005P-104-B-T5: RES, 100 k, 0.1%, 0.063 W, 0402; Manufacturer: Susumu Co Ltd; CompType: Resistor; Value: 100k; Res_ohm: 100000; Power_W: 0.063; Value2: 0.063W; TempCo: 25 ppm/C; SizeArea_mm2: 0.5; SizeX_mm: 1; SizeZ_mm: 0.6; EIA_Code: E192; U/M: EA; AEC Category: Q200; Green_Lifecycle: Active; Green_REACh: Passed
R47 = ERJ-2GEJ101X: RES, 100, 5%, 0.1 W, AEC-Q200 Grade 0, 0402; Manufacturer: Panasonic; CompType: Resistor; Value: 100; Value_Code: 100R; Tolerance_%: 5; Power_W: 0.1; Value2: 0.1W; TempCo: 200 ppm/C; SizeArea_mm2: 0.5; SizeX_mm: 1; SizeZ_mm: 0.6; EIA_Code: E24; U/M: EA; AEC Category: Q200; AEC Qualified: Y; AEC Grade: 0; Green_Lifecycle: Active; Green_REACh: Passed
R53 = CRCW040222K0JNED: RES, 22 k, 5%, 0.063 W, 0402; Manufacturer: Vishay-Dale; CompType: Resistor; Value: 22k; Res_ohm: 22000; Value_Code: 22k0; Tolerance_%: 5; Power_W: 0.063; Value2: 0.063W; VDC_V: 50; TempCo: 200 ppm/C; SizeArea_mm2: 0.5; SizeX_mm: 1; SizeZ_mm: 0.6; EIA_Code: E24; U/M: EA; AEC Category: Q200; Green_Lifecycle: Active; Green_REACh: Passed
R55 R56 = CRCW0402100RJNED: RES, 100, 5%, 0.063 W, 0402; Manufacturer: Vishay-Dale; CompType: Resistor; Value: 100; Value_Code: 100R; Tolerance_%: 5; Power_W: 0.063; Value2: 0.063W; VDC_V: 50; TempCo: 200 ppm/C; SizeArea_mm2: 0.5; SizeX_mm: 1; SizeZ_mm: 0.6; EIA_Code: E24; U/M: EA; AEC Category: Q200; Green_Lifecycle: Active; Green_REACh: Passed
S1-S3 = CMP-0002302-1: Switch, SPST, Off-Mom, 0.05 A, 12 VDC, SMD; Manufacturer: Wurth Elektronik; CurrentRating_mA: 50A; PositionCount: 1; SizeX_mm: 4.3; SizeY_mm: 2.9; SizeZ_mm: 1.9; SizeArea_mm2: 12.47; VDC_V: 12V; SizeAreaWB_mm2: 20.67
TP1 TP2 = CMP-0003825-1: 1mm Test Point, SMT; Manufacturer: Any
U1 = TS318-11C55: THERMOPILE IR SENSOR, HIGH SIGNAL, TO-18, TH; Manufacturer: TE CONNECTIVITY; SymbolCreator: x0199378
U3 = CMP-0073533-3: 350 kHz, Low-Noise, RRIO, CMOS Operational Amplifier for Cost-Sensitive Systems, DGK0008A (VSSOP-8); Alternate PartNumber: TLV2333IDGKT; Alternate Manufacturer: Texas Instruments; SizeAreaWB_mm2: 23.6; SizeZ_mm: 1.1; SizeX_mm: 4.9; SizeY_mm: 3; SizeArea_mm2: 14.7; CompType: IC; AEC Category: Q200; AEC Qualified: N
U4 = CMP-0066526-2: 16-bit Mixed Signal Microcontroller, RHB0032M (VQFN-32); Alternate PartNumber: MSP430I2041TRHBT; Alternate Manufacturer: Texas Instruments; SizeAreaWB_mm2: 49.0; U/M: EA; SizeZ_mm: 1.0; SizeX_mm: 5.0; SizeArea_mm2: 25.0; CompType: IC; AEC Category: Q200; AEC Qualified: N
U5 = CMP-0084264-1: I2C-Compatible (2-wire) Serial EEPROM, SOT-23-5; Manufacturer: Microchip; SizeZ_mm: 1; SizeX_mm: 2.8; SizeY_mm: 2.9; SizeArea_mm2: 8.12; SizeAreaWB_mm2: 14.82
U6 = CMP-0066602-2: Dual-Channel High-Speed ESD Protection, DRL0005A (SOT-OTHER-5); Alternate Manufacturer: Texas Instruments; Green_Lifecycle: Active; SizeAreaWB_mm2: 6.76; Green_REACh: Passed; U/M: EA; SizeZ_mm: 0.6; SizeX_mm: 1.6; SizeArea_mm2: 2.56; CompType: IC
U7 = CMP-0081108-1: 5.5-V, 1.5-A, 100-mohm Load Switch with Output Discharge, DCK0006A (SOT-SC70-6); Alternate PartNumber: TPS22919DCKT; Alternate Manufacturer: Texas Instruments; SizeAreaWB_mm2: 9.3; SizeZ_mm: 1.1; SizeX_mm: 2.1; SizeY_mm: 2; SizeArea_mm2: 4.2; CompType: IC; AEC Qualified: N; AEC Category: Q200
U8 = CMP-0085651-1: +/-6V, Low IQ Ideal Diode with Input Polarity Protection, DCK0006A (SOT-SC70-6); Manufacturer: Texas Instruments; Alternate PartNumber: LM66100DCKT; SizeY_mm: 2; SizeArea_mm2: 4.2; SizeZ_mm: 1.1; SizeX_mm: 2.1; AEC Qualified: N; SizeAreaWB_mm2: 9.3; AEC Category: Q200; CompType: IC
U9 = CMP-0860667-1: 3-A BOOST CONVERTER WITH 0.5V ULTRA-LOW INPUT VOLTAGE, DRL0006A (SOT-5X3-6); Alternate Manufacturer: Texas Instruments; SizeY_mm: 1.6; CompType: IC; SizeZ_mm: 0.6; SizeAreaWB_mm2: 6.76; SizeArea_mm2: 2.56; AEC Category: Q200; AEC Qualified: N

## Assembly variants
Variant of PCB_Project1: not fitted R57 R59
